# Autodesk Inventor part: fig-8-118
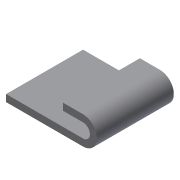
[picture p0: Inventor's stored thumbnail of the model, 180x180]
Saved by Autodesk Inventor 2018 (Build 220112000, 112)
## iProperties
Created: 2009-09
Part Number: fig-8-118
Document SubType Name: Modeling
Designer: Sham
Density: 1 g/cm^3
Material: Generic
Appearance: Default
Author: Sham
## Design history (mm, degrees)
sketch "Sketch1"
  geometry: L1 (-33.976, 22)-(0, 22); L2 (0, 22)-(0, 0); L3 (0, 0)-(-33.976, 0); L4 (-33.976, 0)-(-33.976, 22)
  constraints: 8 end point, 2 parallel, 1 horizontal, 1 perpendicular
extrude "Extrusion1" new body sketch "Sketch1" distance "d0" = 2; taper "d1" = 0 deg
sketch "Sketch2"
  geometry: L1 (-12, 22)-(-12, 0)
  constraints: 2 end point
feature "Bend Part1" sketch "Sketch2" dims "d2" = 2, "d3" = 180 deg
body "Solid1"
